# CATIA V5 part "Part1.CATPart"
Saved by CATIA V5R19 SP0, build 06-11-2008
Part number: Part1
Bounding box of the stored display mesh (mm): x 3.81 to 39.37, y -17.599 to 17.599, z -2.54 to 0.762
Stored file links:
  F:\CAD\ipod\Part1.CATPart
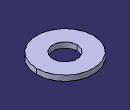
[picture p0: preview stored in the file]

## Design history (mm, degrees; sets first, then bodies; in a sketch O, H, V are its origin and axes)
Body1 (main body)
  DatumSurface1
  DatumCurve1
  DatumCurve2
  Sketch1 on face of DatumSurface1, origin (0, 0, -2.54), H (1, 0, 0), V (0, 1, 0)
    circle A1 centre (21.59, 0) radius 17.78
    reference projected circle E1 centre (21.59, 0) radius 17.78 from edge of DatumCurve1
    circle A2 centre (21.59, 0) radius 7.62
    reference projected circle E2 centre (21.59, 0) radius 7.62 from edge of DatumCurve2
    coincidence: A1 E1, E2 A2
  Pad1: profile Sketch1, direction (0, 0, 1), length 3.302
